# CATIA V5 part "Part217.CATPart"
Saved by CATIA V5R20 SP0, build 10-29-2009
Part number: FA 168700-2 comprimido
Revision: ANY
Definition: UNKNOWN
Nomenclature: FA 168700-2 comprimido
Source: Unknown
Bounding box of the stored display mesh (mm): x -2.8 to 2.8, y 0 to 4.04, z -2.8 to 2.8
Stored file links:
  C:\Users\Utente\Desktop\IO LAVORO\3D X SITO CF\CUMSA\3D files FA\FA 200710-20\Part217.CATPart

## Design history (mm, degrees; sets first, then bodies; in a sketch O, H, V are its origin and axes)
Body1 "Cortar-Extruir1" (main body)
  Solid1: solid without history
